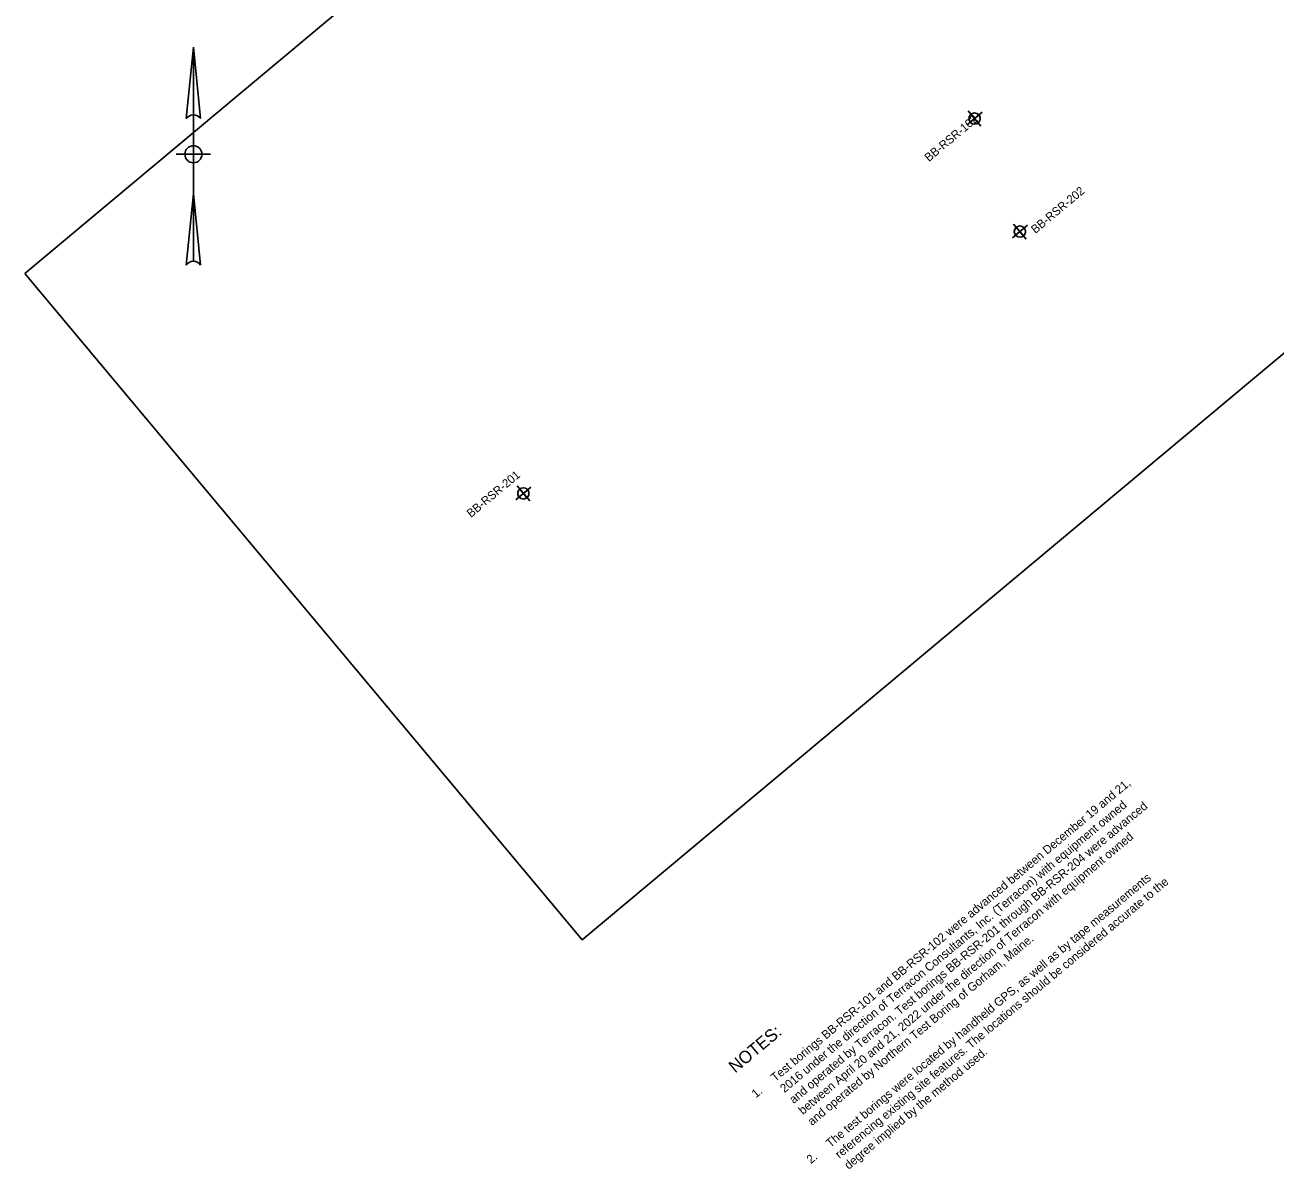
# Model space of a CAD drawing. Extents: x 939197 to 940115, y 627356 to 628138.
# Drawn here: x 939196.7 to 939634.9, y 627356.2 to 627757.3 of the extents above; entities that cross this region are included whole.
import ezdxf

# ---------------------------------------------------------------- set-up
doc = ezdxf.new("R2010")
doc.units = 0
for name, color, linetype in [('ANNOTATION', 7, 'Continuous'), ('H_V CONTROLS', 7, 'Continuous'), ('JUNK', 7, 'Continuous'), ('ROCKS', 7, 'Continuous')]:
    doc.layers.add(name, color=color, linetype=linetype)

msp = doc.modelspace()

# ---------------------------------------------------------------- linework, layer by layer
at = {"layer": 'H_V CONTROLS'}
for p, q in [((939253.23, 627724.47), (939255.73, 627749.47)), ((939255.73, 627749.47), (939255.73, 627674.47)), ((939255.73, 627749.47), (939258.23, 627724.47)), ((939249.73, 627711.97), (939261.73, 627711.97)), ((939253.23, 627673.13), (939255.73, 627698.13)), ((939255.73, 627698.13), (939258.23, 627673.13))]:
    msp.add_line(p, q, dxfattribs=at)
msp.add_circle((939255.73, 627711.97), 3, dxfattribs=at)
for centre in [(939255.73, 627722.81), (939255.73, 627671.47)]:
    msp.add_arc(centre, 3, 33.5573, 146.4427, dxfattribs=at)
at = {"layer": 'JUNK'}
msp.add_lwpolyline([(939196.68, 627670.15), (939756.39, 628138.18), (939951.76, 627904.54), (939392.05, 627436.51)], close=True, dxfattribs=at)
at = {"layer": 'ROCKS'}
for p, q in [((939526.94, 627722.29), (939532.23, 627726.71)), ((939527.38, 627727.14), (939531.79, 627721.86)), ((939542.82, 627682.65), (939548.1, 627687.07)), ((939543.25, 627687.5), (939547.67, 627682.22)), ((939368.76, 627590.87), (939374.04, 627595.29)), ((939369.19, 627595.72), (939373.61, 627590.44))]:
    msp.add_line(p, q, dxfattribs=at)
for points in [[(939529.59, 627724.5), (939528.08, 627723.24), (939527.92, 627723.46), (939527.79, 627723.7), (939527.69, 627723.96), (939527.63, 627724.27), (939527.62, 627724.52), (939527.65, 627724.88), (939527.71, 627725.11), (939527.9, 627725.52), (939528.11, 627725.8), (939528.32, 627726.01)], [(939529.59, 627724.5), (939531.1, 627725.76), (939531.25, 627725.54), (939531.38, 627725.29), (939531.48, 627725.04), (939531.54, 627724.73), (939531.55, 627724.48), (939531.52, 627724.12), (939531.46, 627723.89), (939531.27, 627723.48), (939531.06, 627723.2), (939530.85, 627722.99)], [(939545.46, 627684.86), (939543.95, 627683.6), (939543.79, 627683.82), (939543.66, 627684.07), (939543.57, 627684.33), (939543.5, 627684.63), (939543.49, 627684.88), (939543.53, 627685.24), (939543.59, 627685.47), (939543.78, 627685.88), (939543.99, 627686.17), (939544.2, 627686.37)], [(939545.46, 627684.86), (939546.97, 627686.12), (939547.13, 627685.9), (939547.26, 627685.66), (939547.35, 627685.4), (939547.42, 627685.09), (939547.43, 627684.84), (939547.39, 627684.48), (939547.33, 627684.26), (939547.14, 627683.84), (939546.93, 627683.56), (939546.72, 627683.35)], [(939371.4, 627593.08), (939369.89, 627591.82), (939369.73, 627592.04), (939369.6, 627592.29), (939369.51, 627592.54), (939369.45, 627592.85), (939369.43, 627593.1), (939369.47, 627593.46), (939369.53, 627593.69), (939369.72, 627594.1), (939369.93, 627594.38), (939370.14, 627594.59)], [(939371.4, 627593.08), (939372.91, 627594.34), (939373.07, 627594.12), (939373.2, 627593.88), (939373.29, 627593.62), (939373.36, 627593.31), (939373.37, 627593.06), (939373.33, 627592.7), (939373.28, 627592.47), (939373.09, 627592.06), (939372.88, 627591.78), (939372.67, 627591.57)]]:
    msp.add_lwpolyline(points, close=True, dxfattribs=at)
for centre in [(939529.59, 627724.5), (939545.46, 627684.86), (939371.4, 627593.08)]:
    msp.add_circle(centre, 1.97, dxfattribs=at)

# ---------------------------------------------------------------- texts
at = {"layer": 'ANNOTATION'}
for s, height, p in [('Test borings BB-RSR-101 and BB-RSR-102 were advanced between December 19 and 21, ', 3, (939459.72, 627386.65)), ('2016 under the direction of Terracon Consultants, Inc. (Terracon) with equipment owned ', 3, (939462.94, 627382.8)), ('and operated by Terracon. Test borings BB-RSR-201 through BB-RSR-204 were advanced ', 3, (939466.15, 627378.96)), ('between April 20 and 21, 2022 under the direction of Terracon with equipment owned ', 3, (939469.37, 627375.12)), ('The test borings were located by handheld GPS, as well as by tape measurements ', 3, (939479.01, 627363.59)), ('referencing existing site features. The locations should be considered accurate to the ', 3, (939482.22, 627359.74)), ('and operated by Northern Test Boring of Gorham, Maine.', 3, (939472.58, 627371.27)), ('NOTES:', 4.375, (939445.65, 627389.67)), ('degree implied by the method used.', 3, (939485.44, 627355.9)), ('1.', 3, (939452.93, 627380.97)), ('2.', 3, (939472.21, 627357.91))]:
    msp.add_text(s, height=height, rotation=39.9025, dxfattribs=at).set_placement(p)
at = {"layer": 'ROCKS'}
for s, p in [('BB-RSR-102', (939513.56, 627709.18)), ('BB-RSR-202', (939550.91, 627684)), ('BB-RSR-201', (939353.04, 627584.43))]:
    msp.add_text(s, height=2.953, rotation=39.9025, dxfattribs=at).set_placement(p)

doc.saveas('drawing.dxf')
